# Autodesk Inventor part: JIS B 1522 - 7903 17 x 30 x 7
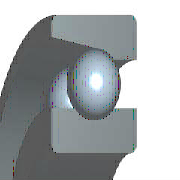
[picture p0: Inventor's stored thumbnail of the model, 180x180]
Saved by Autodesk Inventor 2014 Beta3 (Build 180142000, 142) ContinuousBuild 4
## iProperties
IsCustomPart: 0
Created: 2012-11
Part Number: JIS B 1522 - 7903 17 x 30 x 7
Material: Steel, Mild
Description: Angular Contact Ball Bearing
Document SubType Name: Modeling
Standard: JIS B 1522
Designer: Thomas
Standards Organization: JIS
Language: en-US
Size Designation: 7903 17 x 30 x 7
Categories: <MemberInstance><Categories><Category DisplayName="Shaft Parts" InternalName="7f7aeb1f-a693-4053-b835-cee3144e0d98" Mnemonic="SHFT"><Category DisplayName="Beari
Density: 1 g/cm^3
Appearance: Steel
Author: Thomas
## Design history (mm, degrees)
sketch "Sketch" dims "d1" = 3.38 (= -0.26 x WD + 0.26 x BD)
  geometry: L1 (1.81, 11.75)-(5.19, 11.75); L2 (3.5, 13.44)-(3.5, 10.06); L3 (0, 10.619)-(2.244, 10.619); L4 (0, 8.5)-(7, 8.5); L5 (3.793, 13.414)-(0, 14.083); L6 (7, 10.619)-(7, 8.5); L7 (7, 10.619)-(4.756, 10.619); L8 (7, 12.881)-(4.756, 12.881); L9 (7, 12.881)-(7, 15); L10 (0, 15)-(7, 15); L11 (-2.4, 0)-(14.4, 0) reference; L12 (0, -1.44)-(0, 8.99) reference; 1 further point; 1 other entity
  constraints: 20 end point, 4 point on line, 3 symmetric about line, 2 midpoint, 2 parallel, 1 perpendicular, 14 other
  dimensions: "d0" = 10 deg angle of L8 L5; "d11" = 17 diameter of L4 L11 (= WD); "d12" = 30 diameter of L10 L11 (= BD); "d13" = 7 distance between parallel lines of L6 L12 (= KB); "d14" = 21.238 diameter of L7 L11 (= 0.326 x BD + 0.674 x WD)
revolve "Body" stored, may be unused: angle "d6" = 90 deg
revolve "Ball" stored, may be unused: angle "d8" = 90 deg
pattern_circular "Balls" dims angle "d4" = 360 deg
body "Solid1"
fillet "Fillet1" dims "d2" = 0.3 (= KRS)
other parameters: "WD" = 17 [user parameter; used in 5 equation terms], "BD" = 30 [user parameter; used in 5 equation terms], "KB" = 7 [user parameter; used in 1 equation term], "KRS" = 0.3 [user parameter; used in 1 equation term], "d5" = 0, "d7" = 0, "d9" = 0, "d15" = 0, "d16" = 0, "BC0" = 3300000 [user parameter], "BBA" = 20 deg [user parameter], "BC" = 6000000 [user parameter], "KR1S" = 0.15 [user parameter], "BR" = 15 (= 0.5 x BD) [user parameter], "WR" = 8.5 (= 0.5 x WD) [user parameter]
